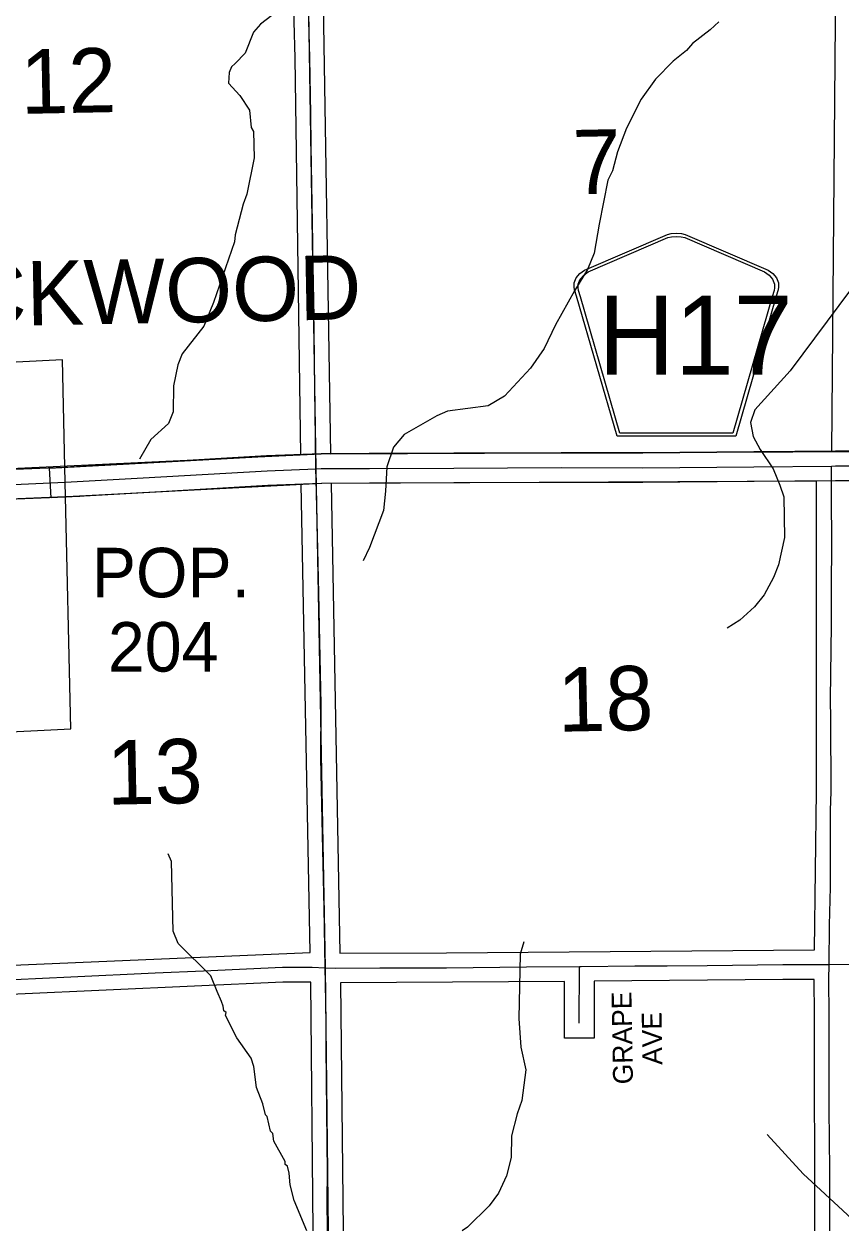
# Model space of a CAD drawing. Extents: x 10133 to 81668, y 7924 to 11018.
# Drawn here: x 11204.3 to 11451.5, y 8510.5 to 8876.1 of the extents above; entities that cross this region are included whole.
import ezdxf

# ---------------------------------------------------------------- set-up
doc = ezdxf.new("R2010")
doc.units = 0
for name, color, linetype in [('tdCoCityStreetMajor', 7, 'Continuous'), ('tdCoCityStreetMinor', 7, 'Continuous'), ('tdCoCoBndryPart', 7, 'Continuous'), ('tdCoCoBndryTxt', 7, 'Continuous'), ('tdCoHydroRiver', 7, 'Continuous'), ('tdCoPriNonDiv', 7, 'Continuous'), ('tdCoRROwnerTxt', 7, 'Continuous'), ('tdCoSectLinePart', 7, 'Continuous'), ('tdCoSectNmbr', 7, 'Continuous'), ('tdCoShieldStRte', 7, 'Continuous'), ('tdCoStrucNonDivPri', 7, 'Continuous'), ('tdCoSurfAsphalt', 7, 'Continuous'), ('tdCoSurfGravel', 7, 'Continuous'), ('tdCoTwpNameTxt', 7, 'Continuous'), ('tdCoUnicrpTwnTxt', 7, 'Continuous')]:
    doc.layers.add(name, color=color, linetype=linetype)

msp = doc.modelspace()

# ---------------------------------------------------------------- linework, layer by layer
at = {"layer": 'tdCoCityStreetMajor'}
for points in [[(11447.99, 8591.27), (11448.13, 8603.15), (11448.42, 8614.69), (11448.46, 8637.88), (11448.65, 8643.65), (11448.53, 8665.37), (11448.42, 8671.77), (11448.73, 8694.06), (11448.73, 8703.53), (11448.77, 8720.58), (11448.73, 8731.2), (11448.7, 8742.26)], [(11295.44, 8590.24), (11295.12, 8608.44), (11294.56, 8630.45), (11294.12, 8653.82), (11294.15, 8670.03), (11293.65, 8693.79), (11293.46, 8703.76)]]:
    msp.add_lwpolyline(points, dxfattribs=at)
at = {"layer": 'tdCoCityStreetMinor'}
for points in [[(11293.46, 8703.76), (11293.21, 8716.99), (11292.65, 8738.22), (11292.62, 8741.42), (11292.51, 8750.76), (11292.25, 8765.48), (11292.06, 8783.38), (11291.84, 8794.07), (11291.69, 8809.94), (11291.51, 8821.74), (11291.21, 8839.17), (11291.06, 8848.97), (11290.8, 8865.95), (11290.47, 8877.16), (11290.13, 8892.79)], [(11447.99, 8591.27), (11454.78, 8591.35), (11473.27, 8591.39), (11490.36, 8591.53), (11508.75, 8591.5), (11515.15, 8591.68), (11522.84, 8591.68), (11534.9, 8591.64), (11555.76, 8591.64), (11583.88, 8591.39), (11599.56, 8591.27), (11600.37, 8591.27)], [(11144.19, 8584.21), (11146.72, 8584.21), (11166.99, 8585.1), (11192.55, 8586.28), (11218.41, 8587.46), (11243.97, 8588.72), (11258.54, 8589.28), (11282.47, 8590.39), (11291.46, 8590.39), (11295.44, 8590.24)], [(11295.44, 8590.24), (11298.6, 8590.13), (11311.92, 8590.2), (11332.19, 8590.28), (11356.38, 8590.53), (11372.39, 8590.64)], [(11296.15, 8510.55), (11296.15, 8510.59), (11296.04, 8519.88), (11296.08, 8528.2), (11295.89, 8546.7), (11295.74, 8566.19), (11295.67, 8573.29), (11295.52, 8585.65), (11295.44, 8590.24)], [(11372.36, 8573.43), (11372.39, 8590.64)], [(11372.39, 8590.64), (11372.95, 8590.65), (11389.12, 8590.79), (11398.92, 8590.79), (11411.02, 8590.98), (11433.99, 8591.2), (11445.38, 8591.24), (11447.99, 8591.27)], [(11448.21, 8510.55), (11448.24, 8518.44), (11448.2, 8528.91), (11448.05, 8547.55), (11448.05, 8558.02), (11448.02, 8576.03), (11447.94, 8586.72), (11447.99, 8591.27)]]:
    msp.add_lwpolyline(points, dxfattribs=at)
at = {"layer": 'tdCoCoBndryPart'}
msp.add_lwpolyline([(11142.2, 8734.26), (11146.06, 8734.43), (11151.11, 8734.63), (11159.46, 8734.96), (11168.15, 8735.32), (11194.35, 8736.41), (11216.71, 8737.34)], dxfattribs=at)
at = {"layer": 'tdCoHydroRiver'}
for points in [[(11283.06, 8881.69), (11275.81, 8876.12), (11273.72, 8873.72), (11271.22, 8867.29), (11268.2, 8864.16), (11267.03, 8863.19), (11266.35, 8861.52), (11266.16, 8858.2), (11269.54, 8854.47), (11272.46, 8850.02), (11273.02, 8844.82), (11273.75, 8843.65), (11273.89, 8835.6), (11271.7, 8824.67), (11270.57, 8821.57), (11268.12, 8812.3), (11267.92, 8810.16), (11261.6, 8791.82), (11258.64, 8784.67), (11252.15, 8776.27), (11250.79, 8772.93), (11249.47, 8766.52), (11249.37, 8758.7), (11248.01, 8755.13), (11242.64, 8750.3), (11239.19, 8744.32)], [(11414.56, 8876.8), (11412, 8874.39), (11406.62, 8870.27), (11404.76, 8868.11), (11400.79, 8864.96), (11395.43, 8859.43), (11391.04, 8853.43), (11386.68, 8844.6), (11383.96, 8837.45), (11382.4, 8831.74), (11381.03, 8828.87), (11378.41, 8815.57), (11376.9, 8806.78), (11374.85, 8801.78), (11370.94, 8795.32), (11365.19, 8785.04), (11361.76, 8777.88), (11357.6, 8771.89), (11349.69, 8763.46), (11344.76, 8760.54), (11332.48, 8758.91), (11329.19, 8757.44), (11319.34, 8751.83), (11316.09, 8747.98), (11314.05, 8742.03), (11313.7, 8734.68), (11313.09, 8728.75), (11308.78, 8717.55), (11306.96, 8713.49)], [(11454.75, 8796.01), (11436.23, 8771.08), (11425.53, 8759.29), (11424.17, 8755.48), (11424.96, 8751.23), (11427.16, 8747.24), (11431.04, 8741.39), (11433.02, 8736.45), (11434.26, 8732.92), (11434.47, 8720.61), (11432.71, 8712.29), (11431.12, 8708.47), (11428.37, 8703.22), (11425.35, 8699.62), (11420.92, 8695.52), (11417.17, 8693.09)], [(11289.86, 8510.55), (11286.07, 8519.79), (11284.81, 8524.51), (11284.51, 8528.06), (11284, 8530.18), (11283.28, 8530.64), (11283.27, 8531.59), (11279.85, 8537.69), (11279.57, 8540.05), (11278.85, 8540.75), (11277.83, 8545.23), (11277.35, 8545.7), (11276.58, 8549), (11274.61, 8553.94), (11273.79, 8560.32), (11273.03, 8562.91), (11268.67, 8568.99), (11265.24, 8575.8), (11265.46, 8576.75), (11264.74, 8577.21), (11264.48, 8578.63), (11263.99, 8580.04), (11262.75, 8583.1), (11260.78, 8587.8), (11250.9, 8597.59), (11249.42, 8601.35), (11248.83, 8622.41), (11247.84, 8624.77)], [(11355.56, 8598.16), (11354.44, 8594.35), (11354.05, 8574.93), (11354.67, 8566.17), (11356.21, 8559.33), (11354.94, 8550.08), (11353.59, 8546.03), (11351.81, 8539.37), (11351.68, 8532.73), (11350.35, 8527.27), (11347.84, 8522.01), (11345.06, 8518.18), (11338.54, 8511.68), (11336.87, 8510.55)], [(11458.82, 8510.55), (11440.09, 8527.82), (11429.24, 8539.72)]]:
    msp.add_lwpolyline(points, dxfattribs=at)
at = {"layer": 'tdCoPriNonDiv'}
for points in [[(11148.61, 8588.79), (11290.86, 8594.89), (11288.19, 8736.74), (11212.46, 8732.6), (11211.97, 8741.59), (11288.07, 8745.74), (11286.31, 8865.85), (11285.73, 8888.14)], [(11595.38, 8746.02), (11596.14, 8813.76), (11597.55, 8822.33), (11597.96, 8884), (11597.96, 8888.46), (11391.68, 8888.71), (11294.72, 8888.45), (11297.06, 8746), (11483.67, 8746.8), (11524.54, 8746.1), (11595.38, 8746.02)], [(11332.16, 8594.77), (11443.55, 8595.73), (11444.15, 8643.71), (11444.22, 8737.72), (11297.19, 8737), (11299.86, 8594.63), (11332.16, 8594.77)], [(11291.82, 8510.55), (11291.02, 8585.89), (11282.58, 8585.89), (11148.78, 8579.8), (11150.34, 8510.55)], [(11443.68, 8510.55), (11443.52, 8576.01), (11443.44, 8586.73), (11434.02, 8586.7), (11376.88, 8586.18), (11376.85, 8568.92), (11367.85, 8568.94), (11367.89, 8586.11), (11300.02, 8585.64), (11300.82, 8510.55)]]:
    msp.add_lwpolyline(points, dxfattribs=at)
at = {"layer": 'tdCoSectLinePart'}
msp.add_lwpolyline([(11216.71, 8737.34), (11240.27, 8738.64), (11277.86, 8740.83), (11292.62, 8741.42), (11294.24, 8741.49), (11308.78, 8741.53), (11334.34, 8741.64), (11366.89, 8741.79), (11391.57, 8741.75), (11425.23, 8742.05), (11448.7, 8742.26), (11449.9, 8742.27), (11483.68, 8742.3)], dxfattribs=at)
at = {"layer": 'tdCoStrucNonDivPri'}
msp.add_lwpolyline([(11449.96, 8888.64), (11448.74, 8746.76)], dxfattribs=at)
at = {"layer": 'tdCoSurfAsphalt'}
msp.add_lwpolyline([(11132.89, 9033.19), (11132.88, 9035.44), (11141.88, 9035.44), (11146.71, 8738.97), (11294.17, 8746), (11308.79, 8746.04), (11334.35, 8746.15), (11366.91, 8746.3), (11391.58, 8746.26), (11425.21, 8746.56), (11449.9, 8746.78), (11483.73, 8746.82), (11483.73, 8737.82), (11483.67, 8737.82), (11449.95, 8737.78), (11425.29, 8737.56), (11391.61, 8737.26), (11366.93, 8737.3), (11334.39, 8737.15), (11308.82, 8737.04), (11294.37, 8737), (11219.06, 8732.98), (11137.76, 8729.58)], close=True, dxfattribs=at)
for points in [[(11483.71, 8746.8), (11449.88, 8746.77), (11425.19, 8746.55), (11391.55, 8746.25), (11366.89, 8746.29), (11334.32, 8746.14), (11308.77, 8746.03), (11294.15, 8745.99), (11277.64, 8745.32), (11240.02, 8743.14), (11216.46, 8741.84)], [(11483.73, 8746.82), (11449.9, 8746.78), (11425.21, 8746.56), (11391.58, 8746.26), (11366.91, 8746.3), (11334.35, 8746.15), (11308.79, 8746.04), (11294.17, 8746), (11277.66, 8745.33), (11240.04, 8743.15), (11216.51, 8741.85)], [(11216.52, 8741.84), (11159.28, 8739.46), (11146.71, 8738.96)], [(11216.51, 8741.85), (11159.3, 8739.47), (11146.73, 8738.97)], [(11483.67, 8737.82), (11449.95, 8737.78), (11425.29, 8737.56), (11391.61, 8737.26), (11366.93, 8737.3), (11334.39, 8737.15), (11308.82, 8737.04), (11294.37, 8737), (11278.1, 8736.34), (11240.55, 8734.16), (11216.95, 8732.86)], [(11483.64, 8737.8), (11449.93, 8737.77), (11425.27, 8737.55), (11391.58, 8737.25), (11366.9, 8737.29), (11334.36, 8737.14), (11308.8, 8737.03), (11294.34, 8736.99), (11278.08, 8736.33), (11240.53, 8734.15), (11216.95, 8732.85)], [(11216.89, 8732.85), (11159.64, 8730.46), (11146.24, 8729.93), (11137.74, 8729.57)], [(11221.16, 8733.04), (11159.67, 8730.48), (11146.27, 8729.94), (11137.76, 8729.58)]]:
    msp.add_lwpolyline(points, dxfattribs=at)
at = {"layer": 'tdCoSurfGravel'}
msp.add_lwpolyline([(11215.88, 8774.39), (11141.64, 8770.66), (11066.99, 8766.91), (11067.49, 8732.16), (11068.57, 8656.96), (11069.54, 8656.98), (11073.06, 8657.04), (11082.86, 8657.3), (11099.88, 8657.81), (11111.83, 8658.26), (11126.77, 8658.59), (11141.64, 8658.85), (11143.35, 8658.9), (11218.36, 8662.6), (11216.71, 8737.34)], close=True, dxfattribs=at)
at = {"layer": 'tdCoTwpNameTxt'}
msp.add_lwpolyline([(11287.46, 9032.68), (11290.13, 8892.79), (11292.62, 8741.42), (11295.44, 8590.24), (11296.31, 8510.55)], dxfattribs=at)
at = {"layer": 'tdCoUnicrpTwnTxt'}
for points in [[(11383.78, 8751.28), (11371.48, 8793.71), (11370.9, 8795.68), (11370.79, 8796.57), (11370.79, 8797.74), (11371.43, 8799.29), (11372.52, 8800.56), (11373.96, 8801.56), (11399.05, 8812.41), (11400.18, 8812.66), (11401.74, 8812.79), (11403.3, 8812.66), (11404.43, 8812.41), (11429.52, 8801.56), (11430.96, 8800.56), (11432.05, 8799.29), (11432.69, 8797.74), (11432.69, 8796.57), (11432.58, 8795.68), (11432, 8793.71), (11419.7, 8751.28)], [(11384.66, 8752.23), (11372.7, 8793.52), (11372.14, 8795.41), (11372.03, 8796.26), (11372.03, 8797.38), (11372.64, 8798.87), (11373.69, 8800.09), (11375.07, 8801.05), (11399.16, 8811.47), (11400.24, 8811.71), (11401.74, 8811.84), (11403.24, 8811.71), (11404.32, 8811.47), (11428.41, 8801.05), (11429.79, 8800.09), (11430.84, 8798.87), (11431.45, 8797.38), (11431.45, 8796.26), (11431.34, 8795.41), (11430.79, 8793.52), (11418.83, 8752.23)]]:
    msp.add_lwpolyline(points, close=True, dxfattribs=at)

# ---------------------------------------------------------------- texts
at = {"layer": 'tdCoCoBndryTxt'}
msp.add_text('PACKWOOD', height=19.5, rotation=1.1105, dxfattribs=at).set_placement((11151.51, 8783.76))
at = {"layer": 'tdCoRROwnerTxt'}
for s, rotation, p in [('12', 1.1421, (11203.32, 8848.93)), ('7', 1.1429, (11370.53, 8824.56)), ('18', 1.1429, (11365.95, 8661.75)), ('13', 1.1422, (11229.44, 8639.64))]:
    msp.add_text(s, height=19.5, rotation=rotation, dxfattribs=at).set_placement(p)
at = {"layer": 'tdCoSectNmbr'}
for s, p in [('POP.', (11224.74, 8702.48)), ('204', (11229.63, 8679.98))]:
    msp.add_text(s, height=15, dxfattribs=at).set_placement(p)
at = {"layer": 'tdCoShieldStRte'}
for s, p in [('GRAPE', (11388.61, 8555)), ('AVE', (11397.51, 8560.87))]:
    msp.add_text(s, height=6, rotation=91, dxfattribs=at).set_placement(p)
at = {"layer": 'tdCoUnicrpTwnTxt'}
msp.add_text('H17', height=24, dxfattribs=at).set_placement((11378.08, 8769.92))

doc.saveas('drawing.dxf')
